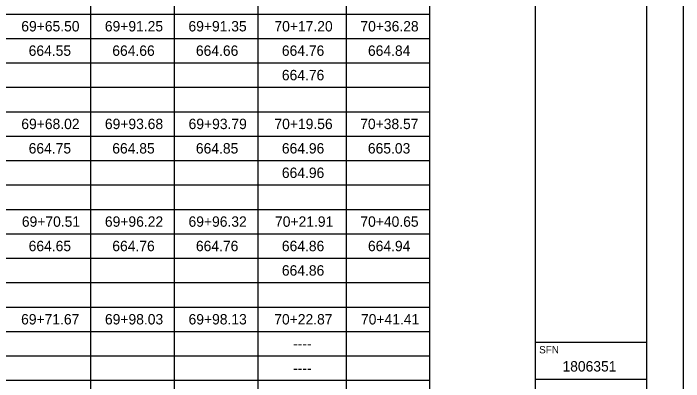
# Model space of a CAD drawing. Extents: x 0 to 34, y 0 to 22.
# Drawn here: x 24.95 to 34, y 4.97 to 9.94 of the extents above; entities that cross this region are included whole.
import ezdxf

# ---------------------------------------------------------------- set-up
doc = ezdxf.new("R2010")
doc.units = 0
for name, color, linetype in [('SH_Border', 7, 'Continuous'), ('SH_Cut_Line', 7, 'Continuous'), ('SH_Data', 7, 'Continuous'), ('SH_Text', 7, 'Continuous')]:
    doc.layers.add(name, color=color, linetype=linetype)

msp = doc.modelspace()

# ---------------------------------------------------------------- linework, layer by layer
at = {"layer": 'SH_Border'}
for p, q in [((32, 0.5), (32, 21.5)), ((32, 5.5), (33.5, 5.5)), ((32, 5), (33.5, 5))]:
    msp.add_line(p, q, dxfattribs=at)
msp.add_lwpolyline([(1.5, 21.5), (33.5, 21.5), (33.5, 0.5), (1.5, 0.5)], close=True, dxfattribs=at)
at = {"layer": 'SH_Cut_Line'}
msp.add_lwpolyline([(0, 0), (34, 0), (34, 22), (0, 22)], close=True, dxfattribs=at)
at = {"layer": 'SH_Text'}
for p, q in [((30.5716, 21.1802), (30.5716, 2.3487)), ((25.9937, 20.0008), (25.9937, 2.3487)), ((27.1223, 20.0008), (27.1223, 2.3487)), ((28.2509, 20.0008), (28.2509, 2.3487)), ((29.4429, 20.0008), (29.4429, 2.3487)), ((2.7998, 9.932), (30.5716, 9.932)), ((4.1947, 9.6023), (30.5716, 9.6023)), ((4.1947, 9.2726), (30.5716, 9.2726)), ((2.7998, 8.9429), (30.5716, 8.9429)), ((2.7998, 8.6131), (30.5716, 8.6131)), ((4.1947, 8.2834), (30.5716, 8.2834)), ((4.1947, 7.9537), (30.5716, 7.9537)), ((2.7998, 7.624), (30.5716, 7.624)), ((2.7998, 7.2943), (30.5716, 7.2943)), ((4.1947, 6.9646), (30.5716, 6.9646)), ((4.1947, 6.6349), (30.5716, 6.6349)), ((2.7998, 6.3052), (30.5716, 6.3052)), ((2.7998, 5.9755), (30.5716, 5.9755)), ((4.1947, 5.6458), (30.5716, 5.6458)), ((4.1947, 5.316), (30.5716, 5.316)), ((4.1947, 4.9863), (30.5716, 4.9863))]:
    msp.add_line(p, q, dxfattribs=at)

# ---------------------------------------------------------------- texts
at = {"layer": 'SH_Data'}
for s, height, p in [('SFN', 0.1, (32.05, 5.35)), ('1806351', 0.14, (32.3649, 5.105))]:
    msp.add_text(s, height=height, dxfattribs=at).set_placement(p)
at = {"layer": 'SH_Text'}
for s, p in [('69+65.50', (25.0591, 9.6971)), ('69+91.25', (26.1871, 9.6971)), ('69+91.35', (27.3157, 9.6971)), ('70+17.20', (28.4767, 9.6971)), ('70+36.28', (29.6371, 9.6971)), ('664.55', (25.1588, 9.3674)), ('664.66', (26.2879, 9.3674)), ('664.66', (27.4165, 9.3674)), ('664.76', (28.5768, 9.3674)), ('664.84', (29.7392, 9.3674)), ('664.76', (28.5768, 9.0377)), ('69+68.02', (25.0594, 8.3783)), ('69+93.68', (26.1878, 8.3783)), ('69+93.79', (27.3176, 8.3783)), ('70+19.56', (28.4765, 8.3783)), ('70+38.57', (29.6344, 8.3783)), ('664.75', (25.1588, 8.0486)), ('664.85', (26.2874, 8.0486)), ('664.85', (27.4161, 8.0486)), ('664.96', (28.5768, 8.0486)), ('665.03', (29.738, 8.0486)), ('664.96', (28.5768, 7.7189)), ('69+70.51', (25.0667, 7.0595)), ('69+96.22', (26.188, 7.0595)), ('69+96.32', (27.3167, 7.0595)), ('70+21.91', (28.4843, 7.0595)), ('70+40.65', (29.6364, 7.0595)), ('664.65', (25.1588, 6.7297)), ('664.76', (26.2879, 6.7297)), ('664.76', (27.4165, 6.7297)), ('664.86', (28.5768, 6.7297)), ('664.94', (29.7392, 6.7297)), ('664.86', (28.5768, 6.4)), ('69+71.67', (25.0565, 5.7406)), ('69+98.03', (26.1885, 5.7406)), ('69+98.13', (27.3171, 5.7406)), ('70+22.87', (28.4741, 5.7406)), ('70+41.41', (29.6446, 5.7406)), ('----', (28.7296, 5.4109)), ('----', (28.7296, 5.0812))]:
    msp.add_text(s, height=0.14, dxfattribs=at).set_placement(p)

doc.saveas('drawing.dxf')
